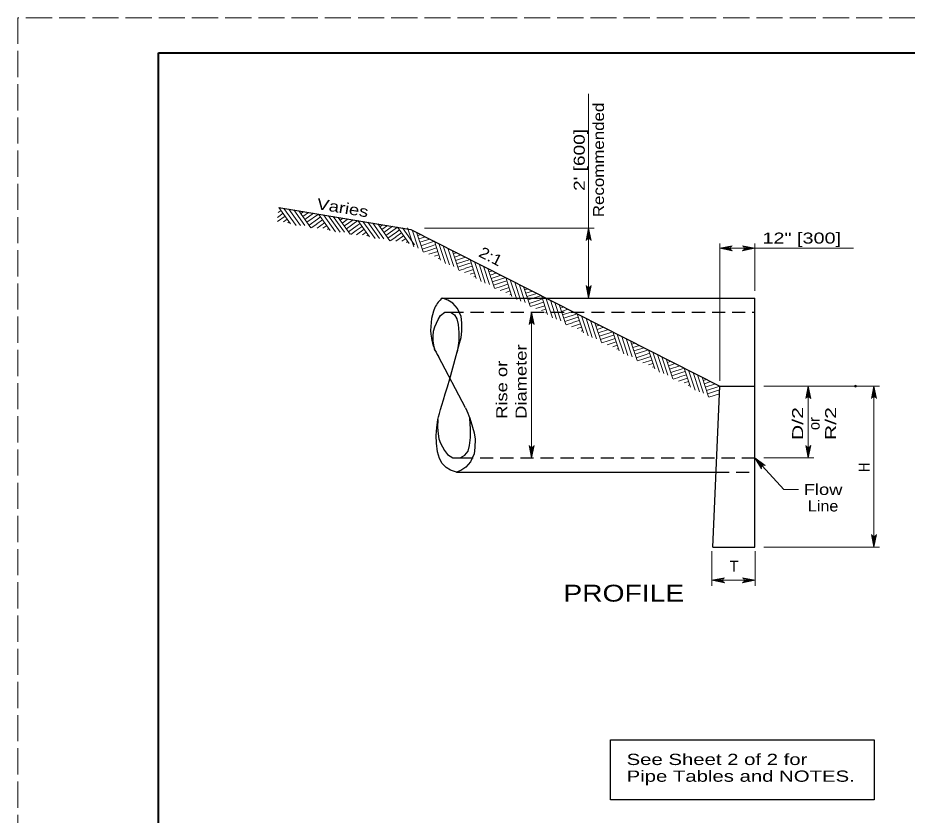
# Model space of a CAD drawing. Extents: x 685.4 to 719.4, y 1059.8 to 1105.8.
# Drawn here: x 685.44 to 698.08, y 1094.44 to 1105.77 of the extents above; entities that cross this region are included whole.
import ezdxf
from ezdxf.enums import TextEntityAlignment as Align

# ---------------------------------------------------------------- set-up
doc = ezdxf.new("R2010")
doc.units = 0
doc.header["$LTSCALE"] = 0.062
doc.header["$PDMODE"] = 32
doc.header["$PDSIZE"] = 0.031
doc.linetypes.add('LONG_DASHED', pattern=[7.5, 6, -1.5])
doc.linetypes.add('MEDIUM_DASHED', pattern=[4.5, 3, -1.5])
doc.layers.add('1', color=7, linetype='Continuous', lineweight=13)

msp = doc.modelspace()

# ---------------------------------------------------------------- linework, layer by layer
at = {"layer": '1', "lineweight": 25}
for p, q in [((687.44108, 1105.27067), (718.94108, 1105.27067)), ((691.47483, 1101.78717), (695.919, 1101.78717)), ((695.919, 1100.53433), (695.919, 1101.78717)), ((691.8055, 1100.22542), (691.42025, 1100.95725)), ((695.31925, 1098.24792), (695.41925, 1100.53433)), ((695.41925, 1100.53433), (695.919, 1100.53433)), ((695.919, 1098.24792), (695.919, 1100.53433)), ((691.67725, 1099.31408), (695.36592, 1099.31408)), ((695.31925, 1098.24792), (695.919, 1098.24792))]:
    msp.add_line(p, q, dxfattribs=at)
at = {"layer": '1'}
for p, q in [((693.55525, 1104.68858), (693.55525, 1101.78717)), ((689.15392, 1103.07333), (689.31958, 1102.84217)), ((689.22408, 1103.06183), (689.39708, 1102.82033)), ((689.13075, 1102.933), (689.2125, 1102.99158)), ((689.1335, 1102.87325), (689.24183, 1102.95075)), ((689.14233, 1103.00325), (689.18317, 1103.03258)), ((689.29408, 1103.05025), (689.46125, 1102.81692)), ((689.36442, 1103.03867), (689.52358, 1102.81642)), ((689.4345, 1103.027), (689.6065, 1102.78692)), ((689.46375, 1102.98617), (689.50458, 1103.01542)), ((689.49308, 1102.94525), (689.57492, 1103.00383)), ((689.52233, 1102.90442), (689.645, 1102.99225)), ((689.55167, 1102.86358), (689.71508, 1102.98067)), ((689.7035, 1102.91058), (689.74442, 1102.93983)), ((689.71508, 1102.98067), (689.88075, 1102.7495)), ((689.78517, 1102.96908), (689.95817, 1102.72767)), ((689.85533, 1102.9575), (690.02242, 1102.72425)), ((689.92558, 1102.94583), (690.08483, 1102.72367)), ((689.99567, 1102.93425), (690.16767, 1102.69417)), ((689.21725, 1102.87133), (689.271, 1102.90992)), ((689.28108, 1102.85533), (689.30025, 1102.86908)), ((689.58092, 1102.82275), (689.70192, 1102.90942)), ((689.61358, 1102.78425), (689.69025, 1102.83917)), ((689.69192, 1102.84033), (689.77375, 1102.89892)), ((689.69467, 1102.78042), (689.80292, 1102.85808)), ((689.77833, 1102.77867), (689.83217, 1102.81717)), ((690.02492, 1102.8935), (690.06575, 1102.92275)), ((690.05425, 1102.85258), (690.136, 1102.91117)), ((690.08358, 1102.81167), (690.20617, 1102.89958)), ((690.11283, 1102.77092), (690.27625, 1102.888)), ((690.142, 1102.73008), (690.26308, 1102.81667)), ((690.25308, 1102.74767), (690.33483, 1102.80617)), ((690.26467, 1102.81783), (690.30558, 1102.84717)), ((690.27625, 1102.888), (690.44192, 1102.65675)), ((690.34633, 1102.87642), (690.51933, 1102.635)), ((690.4165, 1102.86483), (690.58358, 1102.63158)), ((690.48667, 1102.85317), (690.646, 1102.631)), ((690.55683, 1102.84158), (690.72892, 1102.6015)), ((690.58608, 1102.80075), (690.627, 1102.83)), ((690.61542, 1102.75992), (690.69717, 1102.81842)), ((690.64475, 1102.719), (690.76733, 1102.80683)), ((689.84225, 1102.76267), (689.8615, 1102.77642)), ((690.17475, 1102.6915), (690.25142, 1102.7465)), ((690.25583, 1102.68775), (690.36408, 1102.76542)), ((690.3395, 1102.68592), (690.39333, 1102.7245)), ((690.4035, 1102.66992), (690.42267, 1102.68367)), ((690.67392, 1102.67817), (690.8375, 1102.79525)), ((690.70317, 1102.63733), (690.82425, 1102.724)), ((690.81425, 1102.65492), (690.896, 1102.7135)), ((690.82592, 1102.72517), (690.86667, 1102.7545)), ((690.8375, 1102.79525), (691.00308, 1102.56408)), ((690.9075, 1102.78367), (691.0805, 1102.54225)), ((690.98258, 1102.78717), (691.07167, 1102.51433)), ((691.04608, 1102.755), (691.131, 1102.49517)), ((691.10942, 1102.72275), (691.20108, 1102.442)), ((691.12508, 1102.675), (691.17283, 1102.69058)), ((693.63392, 1102.78167), (691.22108, 1102.78167)), ((693.5305, 1102.6195), (693.55525, 1102.78167)), ((693.54083, 1102.62567), (693.55525, 1102.78167)), ((693.55525, 1102.78167), (693.55525, 1102.45542)), ((693.55525, 1102.6285), (693.55525, 1102.78167)), ((693.56658, 1102.62683), (693.55525, 1102.78167)), ((693.57767, 1102.62142), (693.55525, 1102.78167)), ((690.73592, 1102.59883), (690.81267, 1102.65367)), ((690.817, 1102.59508), (690.92525, 1102.67267)), ((690.90067, 1102.59325), (690.95458, 1102.63183)), ((690.96467, 1102.57725), (690.98383, 1102.591)), ((691.14067, 1102.62717), (691.23625, 1102.65833)), ((691.15633, 1102.57942), (691.29967, 1102.62625)), ((691.17192, 1102.53158), (691.36308, 1102.59408)), ((691.36308, 1102.59408), (691.45133, 1102.32375)), ((691.42633, 1102.56192), (691.51867, 1102.2795)), ((695.41925, 1102.56175), (695.41925, 1100.6115)), ((695.919, 1101.88758), (695.919, 1102.56175)), ((691.1875, 1102.48392), (691.329, 1102.53008)), ((691.207, 1102.43733), (691.29675, 1102.46658)), ((691.28325, 1102.40933), (691.40983, 1102.45067)), ((691.29867, 1102.46725), (691.39425, 1102.49842)), ((691.33092, 1102.53067), (691.37858, 1102.54633)), ((691.48975, 1102.52975), (691.57883, 1102.25692)), ((691.55325, 1102.4975), (691.63808, 1102.23767)), ((691.61658, 1102.46533), (691.70833, 1102.18458)), ((691.63225, 1102.41758), (691.68, 1102.43317)), ((695.5795, 1102.51758), (695.41925, 1102.49517)), ((695.574, 1102.5065), (695.41925, 1102.49517)), ((695.57242, 1102.49517), (695.41925, 1102.49517)), ((695.57525, 1102.48083), (695.41925, 1102.49517)), ((695.58133, 1102.47042), (695.41925, 1102.49517)), ((695.41925, 1102.49517), (697.31833, 1102.49517)), ((695.75683, 1102.47042), (695.919, 1102.49517)), ((695.75875, 1102.51758), (695.919, 1102.49517)), ((695.763, 1102.48083), (695.919, 1102.49517)), ((695.76417, 1102.5065), (695.919, 1102.49517)), ((695.76583, 1102.49517), (695.919, 1102.49517)), ((691.3625, 1102.38233), (691.42542, 1102.40292)), ((691.41858, 1102.34792), (691.44108, 1102.35525)), ((691.64783, 1102.36967), (691.74342, 1102.40092)), ((691.66342, 1102.322), (691.80683, 1102.36875)), ((691.67908, 1102.27417), (691.87025, 1102.33667)), ((691.87025, 1102.33667), (691.9585, 1102.06625)), ((691.9335, 1102.3045), (692.02583, 1102.02208)), ((691.69467, 1102.22642), (691.83617, 1102.27267)), ((691.71425, 1102.17992), (691.80392, 1102.20917)), ((691.79042, 1102.15192), (691.917, 1102.19325)), ((691.80583, 1102.20983), (691.9015, 1102.241)), ((691.83808, 1102.27325), (691.88583, 1102.28892)), ((691.99692, 1102.27233), (692.086, 1101.9995)), ((692.06042, 1102.24008), (692.14525, 1101.98025)), ((692.12375, 1102.20783), (692.2155, 1101.92708)), ((692.13933, 1102.16017), (692.18717, 1102.17575)), ((691.86967, 1102.12492), (691.93258, 1102.1455)), ((691.92575, 1102.09042), (691.94817, 1102.09775)), ((692.155, 1102.11225), (692.25067, 1102.1435)), ((692.17058, 1102.06458), (692.314, 1102.11133)), ((692.18625, 1102.01675), (692.37742, 1102.07917)), ((692.37742, 1102.07917), (692.46567, 1101.80883)), ((692.20183, 1101.969), (692.34325, 1102.01525)), ((692.22142, 1101.92242), (692.311, 1101.95167)), ((692.29758, 1101.8945), (692.42425, 1101.93575)), ((692.31292, 1101.95233), (692.40867, 1101.98358)), ((692.34517, 1102.01583), (692.393, 1102.0315)), ((692.44067, 1102.04708), (692.53292, 1101.76467)), ((692.50408, 1102.01492), (692.59325, 1101.74208)), ((692.56758, 1101.98267), (692.65242, 1101.72283)), ((692.63092, 1101.95042), (692.72267, 1101.66967)), ((693.53283, 1101.94742), (693.55525, 1101.78717)), ((693.54392, 1101.942), (693.55525, 1101.78717)), ((693.58008, 1101.94933), (693.55525, 1101.78717)), ((693.56967, 1101.94317), (693.55525, 1101.78717)), ((693.55525, 1101.94033), (693.55525, 1101.78717)), ((692.37683, 1101.8675), (692.43975, 1101.88808)), ((692.433, 1101.833), (692.45533, 1101.84033)), ((692.6465, 1101.90275), (692.69433, 1101.91833)), ((692.66217, 1101.85483), (692.75783, 1101.88608)), ((692.67775, 1101.80708), (692.82117, 1101.85392)), ((692.69342, 1101.75933), (692.88458, 1101.82175)), ((692.88458, 1101.82175), (692.97275, 1101.55142)), ((692.709, 1101.71158), (692.85042, 1101.75783)), ((692.72858, 1101.665), (692.81817, 1101.69425)), ((692.80475, 1101.637), (692.93142, 1101.67833)), ((692.82008, 1101.69492), (692.91575, 1101.72617)), ((692.85233, 1101.75842), (692.90017, 1101.77408)), ((692.94792, 1101.78958), (693.04008, 1101.50717)), ((693.01125, 1101.7575), (693.10042, 1101.48458)), ((693.07475, 1101.72525), (693.15958, 1101.46542)), ((693.13817, 1101.693), (693.22983, 1101.41225)), ((692.72033, 1101.42517), (692.74517, 1101.58733)), ((692.73075, 1101.43133), (692.74517, 1101.58733)), ((692.74517, 1101.43417), (692.74517, 1101.58733)), ((692.7565, 1101.4325), (692.74517, 1101.58733)), ((692.76758, 1101.42708), (692.74517, 1101.58733)), ((692.884, 1101.61008), (692.947, 1101.63067)), ((692.94017, 1101.57558), (692.96258, 1101.58292)), ((693.15367, 1101.64525), (693.2015, 1101.66083)), ((693.16933, 1101.59742), (693.265, 1101.62867)), ((693.18492, 1101.54967), (693.32833, 1101.5965)), ((693.2005, 1101.50183), (693.39167, 1101.56433)), ((693.39167, 1101.56433), (693.48, 1101.294)), ((693.21617, 1101.45417), (693.35758, 1101.50033)), ((693.23575, 1101.40758), (693.32533, 1101.43683)), ((693.312, 1101.37958), (693.43858, 1101.42092)), ((693.32725, 1101.4375), (693.42292, 1101.46875)), ((693.3595, 1101.50092), (693.40733, 1101.51658)), ((693.45508, 1101.53217), (693.54725, 1101.24975)), ((693.51842, 1101.5), (693.6075, 1101.22717)), ((693.58192, 1101.46783), (693.66683, 1101.20792)), ((693.64533, 1101.43558), (693.737, 1101.15483)), ((693.39117, 1101.35258), (693.45417, 1101.37317)), ((693.44733, 1101.31817), (693.46975, 1101.3255)), ((693.66092, 1101.38783), (693.70867, 1101.40342)), ((693.6765, 1101.34), (693.77217, 1101.37117)), ((693.69208, 1101.29225), (693.83558, 1101.339)), ((693.70767, 1101.2445), (693.89883, 1101.30692)), ((693.89883, 1101.30692), (693.98717, 1101.03658)), ((693.72333, 1101.19675), (693.86475, 1101.24292)), ((693.74292, 1101.15017), (693.83258, 1101.17942)), ((693.81908, 1101.12217), (693.94575, 1101.1635)), ((693.8345, 1101.18008), (693.93008, 1101.21125)), ((693.86667, 1101.2435), (693.9145, 1101.25917)), ((693.96225, 1101.27475), (694.05442, 1100.99233)), ((694.02567, 1101.24258), (694.11467, 1100.96975)), ((694.08908, 1101.21033), (694.174, 1100.9505)), ((694.1525, 1101.17817), (694.24417, 1100.89742)), ((693.89833, 1101.09517), (693.96133, 1101.11575)), ((693.9545, 1101.06067), (693.97692, 1101.068)), ((694.16808, 1101.13042), (694.21575, 1101.146)), ((694.18375, 1101.0825), (694.27933, 1101.11375)), ((694.19933, 1101.03483), (694.34275, 1101.08158)), ((694.21483, 1100.98708), (694.406, 1101.0495)), ((694.406, 1101.0495), (694.49433, 1100.77908)), ((694.23042, 1100.93925), (694.372, 1100.9855)), ((694.25008, 1100.89275), (694.33975, 1100.92192)), ((694.34167, 1100.92258), (694.43725, 1100.95383)), ((694.37392, 1100.98608), (694.42158, 1101.00175)), ((694.46942, 1101.01733), (694.56158, 1100.73492)), ((694.53283, 1100.98517), (694.62183, 1100.71233)), ((694.59625, 1100.95292), (694.68117, 1100.69308)), ((694.65967, 1100.92067), (694.75133, 1100.63992)), ((694.32625, 1100.86475), (694.45283, 1100.90608)), ((694.4055, 1100.83775), (694.4685, 1100.85833)), ((694.46167, 1100.80325), (694.48408, 1100.81058)), ((694.67525, 1100.873), (694.723, 1100.88858)), ((694.69092, 1100.82508), (694.7865, 1100.85633)), ((694.7065, 1100.77733), (694.84983, 1100.82417)), ((694.72208, 1100.72967), (694.91317, 1100.792)), ((694.91317, 1100.792), (695.0015, 1100.52167)), ((694.73758, 1100.68183), (694.87917, 1100.72808)), ((694.75717, 1100.63525), (694.84692, 1100.6645)), ((694.84883, 1100.66517), (694.94442, 1100.69642)), ((694.88108, 1100.72867), (694.92875, 1100.74433)), ((694.97658, 1100.75983), (695.06883, 1100.47742)), ((695.03992, 1100.72775), (695.129, 1100.45492)), ((695.10342, 1100.6955), (695.18833, 1100.43567)), ((695.16683, 1100.66325), (695.25858, 1100.3825)), ((694.83342, 1100.60733), (694.96, 1100.64858)), ((694.91267, 1100.58033), (694.97567, 1100.60092)), ((694.96883, 1100.54583), (694.99125, 1100.55317)), ((695.18242, 1100.61558), (695.23017, 1100.63108)), ((695.19808, 1100.56767), (695.29367, 1100.59892)), ((695.21367, 1100.51992), (695.357, 1100.56675)), ((695.22925, 1100.47217), (695.42042, 1100.53458)), ((696.04708, 1100.53433), (697.68933, 1100.53433)), ((696.65125, 1100.37217), (696.67608, 1100.53433)), ((696.66167, 1100.37833), (696.67608, 1100.53433)), ((696.67608, 1100.38117), (696.67608, 1100.53433)), ((696.68733, 1100.3795), (696.67608, 1100.53433)), ((696.6985, 1100.37408), (696.67608, 1100.53433)), ((697.58592, 1100.37217), (697.61067, 1100.53433)), ((697.59625, 1100.37833), (697.61067, 1100.53433)), ((697.61067, 1100.38117), (697.61067, 1100.53433)), ((697.622, 1100.3795), (697.61067, 1100.53433)), ((697.63308, 1100.37408), (697.61067, 1100.53433)), ((695.24483, 1100.42442), (695.41683, 1100.48058)), ((695.26433, 1100.37783), (695.4145, 1100.42675)), ((691.86642, 1100.07292), (691.86458, 1100.075)), ((691.87308, 1100.0525), (691.86583, 1100.06125)), ((691.41175, 1100.0195), (691.40792, 1100.02408)), ((692.72275, 1099.67425), (692.74517, 1099.514)), ((692.73383, 1099.66883), (692.74517, 1099.514)), ((692.76992, 1099.67617), (692.74517, 1099.514)), ((692.75958, 1099.67), (692.74517, 1099.514)), ((692.74517, 1099.66717), (692.74517, 1099.514)), ((696.65358, 1099.67425), (696.67608, 1099.514)), ((696.66475, 1099.66883), (696.67608, 1099.514)), ((696.70083, 1099.67617), (696.67608, 1099.514)), ((696.69042, 1099.67), (696.67608, 1099.514)), ((696.67608, 1099.66717), (696.67608, 1099.514)), ((696.02233, 1099.40092), (695.919, 1099.514)), ((696.01358, 1099.38917), (695.919, 1099.514)), ((696.01008, 1099.37758), (695.919, 1099.514)), ((696.03175, 1099.40733), (695.919, 1099.514)), ((696.04367, 1099.41083), (695.919, 1099.514)), ((696.75475, 1099.514), (696.04708, 1099.514)), ((697.58825, 1098.40817), (697.61067, 1098.24792)), ((697.59933, 1098.40275), (697.61067, 1098.24792)), ((697.6355, 1098.41), (697.61067, 1098.24792)), ((697.62508, 1098.40392), (697.61067, 1098.24792)), ((697.61067, 1098.40108), (697.61067, 1098.24792)), ((695.30842, 1098.18942), (695.30842, 1097.69783)), ((695.921, 1098.18942), (695.921, 1097.69783)), ((696.04708, 1098.24792), (697.68933, 1098.24792)), ((695.46867, 1097.79892), (695.30842, 1097.7765)), ((695.46325, 1097.78783), (695.30842, 1097.7765)), ((695.921, 1097.7765), (695.30842, 1097.7765)), ((695.46158, 1097.7765), (695.30842, 1097.7765)), ((695.46442, 1097.76217), (695.30842, 1097.7765)), ((695.47058, 1097.75175), (695.30842, 1097.7765)), ((695.75883, 1097.75175), (695.921, 1097.7765)), ((695.76075, 1097.79892), (695.921, 1097.7765)), ((695.765, 1097.76217), (695.921, 1097.7765)), ((695.76617, 1097.78783), (695.921, 1097.7765)), ((695.76783, 1097.7765), (695.921, 1097.7765))]:
    msp.add_line(p, q, dxfattribs=at)
at = {"layer": '1', "linetype": 'MEDIUM_DASHED', "lineweight": 25}
for p, q in [((691.59192, 1101.588), (695.919, 1101.58733)), ((691.72708, 1099.51425), (695.919, 1099.514)), ((695.36592, 1099.31408), (695.919, 1099.31408))]:
    msp.add_line(p, q, dxfattribs=at)
at = {"layer": '1', "linetype": 'LONG_DASHED'}
msp.add_lwpolyline([(685.44108, 1083.77067), (719.44108, 1083.77067), (719.44108, 1105.77067), (685.44108, 1105.77067)], close=True, dxfattribs=at)
at = {"layer": '1', "lineweight": 25}
for points in [[(718.94108, 1084.27067), (687.44108, 1084.27067), (687.44108, 1105.27067)], [(689.15392, 1103.07333), (691.02892, 1102.76367), (695.42042, 1100.53458)], [(691.57742, 1100.6185), (691.72117, 1101.1435), (691.74192, 1101.22583), (691.75517, 1101.31417), (691.75483, 1101.4325), (691.74125, 1101.52258), (691.6925, 1101.63967), (691.626, 1101.71267), (691.55183, 1101.75867), (691.49233, 1101.78258), (691.47483, 1101.78725)], [(691.86425, 1100.07967), (691.906, 1099.95325), (691.92683, 1099.87092), (691.94008, 1099.78258), (691.93975, 1099.66425), (691.92617, 1099.57417), (691.87742, 1099.45708), (691.81092, 1099.38408), (691.73675, 1099.33808), (691.67725, 1099.31408), (691.58975, 1099.34142), (691.53017, 1099.38042), (691.47483, 1099.43375), (691.43317, 1099.5085), (691.40542, 1099.60275), (691.39175, 1099.72517), (691.38892, 1099.835), (691.39533, 1099.94725), (691.41375, 1100.06033)], [(691.41375, 1100.06033), (691.4085, 1099.95375), (691.41642, 1099.85917), (691.426, 1099.78675), (691.45067, 1099.72508), (691.50508, 1099.6185), (691.55042, 1099.56192), (691.62508, 1099.5165), (691.72708, 1099.51425), (691.795, 1099.55508), (691.84117, 1099.612), (691.86025, 1099.69192), (691.876, 1099.80517), (691.87758, 1099.92225), (691.86425, 1100.07967)]]:
    msp.add_lwpolyline(points, dxfattribs=at)
at = {"layer": '1', "lineweight": 40}
msp.add_lwpolyline([(687.44108, 1105.27067), (718.94108, 1105.27067), (718.94108, 1084.27067), (687.44108, 1084.27067)], close=True, dxfattribs=at)
at = {"layer": '1'}
for points in [[(693.51983, 1102.60467), (693.55525, 1102.78167), (693.59067, 1102.60467)], [(695.59625, 1102.45983), (695.41925, 1102.49517), (695.59625, 1102.53058)], [(695.742, 1102.45983), (695.919, 1102.49517), (695.742, 1102.53058)], [(693.59067, 1101.96417), (693.55525, 1101.78717), (693.51983, 1101.96417)], [(692.70975, 1101.41033), (692.74517, 1101.58733), (692.78058, 1101.41033)], [(692.74517, 1101.58733), (692.74517, 1100.49075), (692.74517, 1099.514)], [(696.64067, 1100.35733), (696.67608, 1100.53433), (696.71142, 1100.35733)], [(696.67608, 1100.53433), (696.67608, 1099.86008), (696.67608, 1099.514)], [(697.57525, 1100.35733), (697.61067, 1100.53433), (697.64608, 1100.35733)], [(697.61067, 1100.53433), (697.61067, 1099.11025), (697.61067, 1098.24792)], [(692.78058, 1099.691), (692.74517, 1099.514), (692.70975, 1099.691)], [(696.71142, 1099.691), (696.67608, 1099.514), (696.64067, 1099.691)], [(696.01225, 1099.3595), (695.919, 1099.514), (696.0645, 1099.40725)], [(695.919, 1099.514), (696.33058, 1099.06358), (696.53708, 1099.06358)], [(697.64608, 1098.42492), (697.61067, 1098.24792), (697.57525, 1098.42492)], [(695.48542, 1097.74117), (695.30842, 1097.7765), (695.48542, 1097.81192)], [(695.744, 1097.74117), (695.921, 1097.7765), (695.744, 1097.81192)]]:
    msp.add_lwpolyline(points, dxfattribs=at)
at = {"layer": '1', "linetype": 'LONG_DASHED', "lineweight": 25}
msp.add_lwpolyline([(691.37083, 1101.0405), (691.34683, 1101.17617), (691.3435, 1101.24308), (691.35117, 1101.3155), (691.37083, 1101.37717), (691.41433, 1101.48375), (691.45058, 1101.54033), (691.51042, 1101.58575), (691.59192, 1101.588), (691.64633, 1101.54717), (691.68325, 1101.49017), (691.6985, 1101.41033), (691.71108, 1101.29708), (691.71242, 1101.18), (691.68742, 1101.01933)], dxfattribs=at)
at = {"layer": '1', "lineweight": 25}
msp.add_lwpolyline([(693.86808, 1095.508), (697.61525, 1095.508), (697.61525, 1094.656), (693.86808, 1094.656)], close=True, dxfattribs=at)
at = {"layer": '1'}
for centre, start, end in [((693.5553, 1102.59033), 22.08782, 157.91395), ((695.61051, 1102.49524), 112.08782, 247.91395), ((695.72769, 1102.49524), 292.08605, 67.91218), ((693.55522, 1101.97849), 202.08782, 337.91395), ((692.74518, 1101.39602), 22.08782, 157.91395), ((696.67608, 1100.34304), 22.08782, 157.91395), ((697.61073, 1100.34304), 22.08782, 157.91395), ((692.74511, 1099.70531), 202.08782, 337.91395), ((696.67601, 1099.70531), 202.08782, 337.91395), ((696.04806, 1099.37283), 64.51267, 200.33879), ((697.61065, 1098.4392), 202.08782, 337.91395), ((695.49973, 1097.77657), 112.08782, 247.91395), ((695.72969, 1097.77657), 292.08605, 67.91218)]:
    msp.add_arc(centre, 0.0382, start, end, dxfattribs=at)
at = {"layer": '1', "lineweight": 25}
for centre, major_axis, start_param, end_param in [((691.67632, 1101.44699), (0, 0.41467), 0.60853498, 1.05234758), ((691.89379, 1101.34762), (0, -0.68731), 4.25283424, 4.90421148), ((691.83806, 1101.3369), (0, -0.62098), 4.9073919, 5.37012799)]:
    msp.add_ellipse(centre, major_axis=major_axis, ratio=0.850089, start_param=start_param, end_param=end_param, dxfattribs=at)
for points in [[(691.41375, 1100.06033), (691.43542, 1100.15883), (691.48092, 1100.31683), (691.58367, 1100.638)], [(691.8055, 1100.22542), (691.82858, 1100.17175), (691.848, 1100.12325), (691.86425, 1100.07967)]]:
    msp.add_open_spline(points, degree=3, dxfattribs=at)
at = {"layer": '1'}
msp.add_point((697.348, 1100.53433), dxfattribs=at)

# ---------------------------------------------------------------- texts
for s, width, p in [('Recommended', 1.15, (693.77383, 1103.75038)), ("2' [600]", 1.3, (693.49983, 1103.75042)), ('D/2', 1.45, (696.604, 1100.00221)), ('R/2', 1.45, (697.07333, 1100.00217))]:
    msp.add_text(s, height=0.156, rotation=90, dxfattribs=dict(at, width=width)).set_placement(p, align=Align.CENTER)
for s, rotation, width, p in [('Varies', 350.62, 1.25, (689.68183, 1103.05333)), ('2:1', 333.088, 1.15, (691.9795, 1102.38458)), ('Diameter', 90, 1.25, (692.67217, 1100.06983)), ('Rise or', 90, 1.25, (692.39817, 1100.06983)), ('H', 90, 0.9, (697.54792, 1099.31342))]:
    msp.add_text(s, height=0.156, rotation=rotation, dxfattribs=dict(at, width=width)).set_placement(p)
for s, height, width, p in [('12" [300]', 0.156, 1.35, (696.02592, 1102.5615)), ('PROFILE', 0.24, 1.25, (693.19617, 1097.472)), ('See Sheet 2 of 2 for', 0.16, 1.35, (694.09517, 1095.14925)), ('Pipe Tables and NOTES.', 0.16, 1.35, (694.09517, 1094.91125))]:
    msp.add_text(s, height=height, dxfattribs=dict(at, width=width)).set_placement(p)
msp.add_text('or', height=0.156, rotation=90, dxfattribs=at).set_placement((696.83867, 1100.00221), align=Align.CENTER)
for s, width, p in [('Flow', 1.25, (696.88783, 1098.98833)), ('Line', 1.1, (696.88783, 1098.75367))]:
    msp.add_text(s, height=0.156, dxfattribs=dict(at, width=width)).set_placement(p, align=Align.CENTER)
msp.add_text('T', height=0.156, dxfattribs=at).set_placement((695.55908, 1097.89783))

doc.saveas('drawing.dxf')
